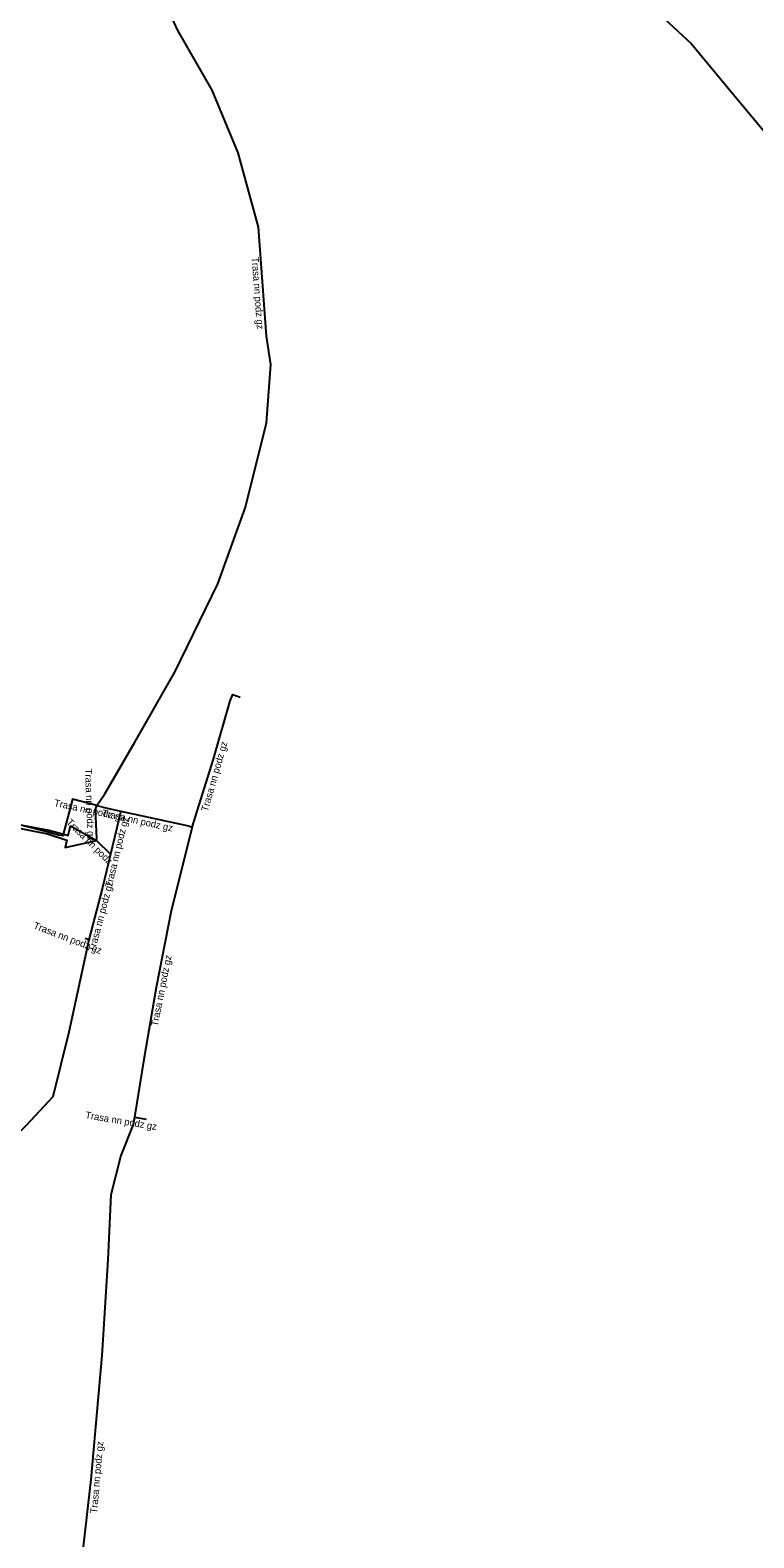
# Model space of a CAD drawing. Extents: x -746106 to -745701, y -1027695 to -1027301.
# Drawn here: x -745858.4 to -745806.6, y -1027605.4 to -1027497.7 of the extents above; entities that cross this region are included whole.
import ezdxf

# ---------------------------------------------------------------- set-up
doc = ezdxf.new("R2010")
doc.units = 0
for name, color, linetype in [('Popiskový text - Ostatní atributy Trasy', 7, 'Continuous'), ('Spojnice NN', 7, 'Continuous'), ('Spojnice VN', 7, 'Continuous')]:
    doc.layers.add(name, color=color, linetype=linetype)

msp = doc.modelspace()

# ---------------------------------------------------------------- linework, layer by layer
at = {"layer": 'Spojnice NN'}
for points in [[(-745833.38, -1027473.7), (-745832.61, -1027474.52), (-745830.56, -1027477.68), (-745830.02, -1027478.96), (-745827.99, -1027481.12), (-745826.54, -1027481.65), (-745825.7, -1027482.38), (-745822.31, -1027485.93), (-745822.27, -1027486.77), (-745822.24, -1027487.41), (-745817.88, -1027491.99), (-745814.57, -1027495.33), (-745813.05, -1027496.89), (-745811.1, -1027498.69), (-745808.13, -1027502.3), (-745805.97, -1027504.9), (-745801.77, -1027509.96)], [(-745853.61, -1027553.12), (-745853.04, -1027552.29), (-745850.88, -1027548.6), (-745848.01, -1027543.54), (-745844.95, -1027537.29), (-745842.98, -1027531.81), (-745841.48, -1027525.78), (-745841.16, -1027521.62), (-745841.47, -1027519.58), (-745842.05, -1027511.8), (-745843.5, -1027506.49), (-745845.35, -1027502.01), (-745847.83, -1027497.69), (-745851.14, -1027490.42), (-745851.64, -1027489.29), (-745851.73, -1027488.18), (-745850.5, -1027485.82), (-745849.88, -1027484.09), (-745850.26, -1027482.81), (-745850.23, -1027482.2)], [(-745853.61, -1027553.12), (-745855.35, -1027552.67), (-745856.03, -1027555.3), (-745856.34, -1027555.24), (-745857.62, -1027554.88), (-745859.38, -1027554.44), (-745860.45, -1027553.37), (-745862.22, -1027551.01), (-745863.97, -1027548.54), (-745864.71, -1027547.66), (-745867.54, -1027543.32), (-745868.03, -1027543.12), (-745868.49, -1027543.06), (-745873.93, -1027545.55), (-745875.45, -1027546.09), (-745878.52, -1027546.57), (-745882.46, -1027546.81)], [(-745846.79, -1027554.68), (-745845.29, -1027549.89), (-745844.07, -1027545.64), (-745843.89, -1027545.19), (-745843.35, -1027545.39)], [(-745853.62, -1027555.63), (-745853.61, -1027555.49), (-745853.69, -1027553.42), (-745853.61, -1027553.12)], [(-745853.61, -1027553.12), (-745852.86, -1027553.32), (-745851.88, -1027553.53)], [(-745851.88, -1027553.53), (-745852.62, -1027556.61)], [(-745851.88, -1027553.53), (-745847.04, -1027554.58), (-745846.79, -1027554.68)], [(-745853.62, -1027555.63), (-745852.62, -1027556.61)], [(-745846.79, -1027554.68), (-745848.28, -1027560.64), (-745849.36, -1027566.13), (-745850.25, -1027571.26), (-745850.92, -1027575.4)], [(-745852.62, -1027556.61), (-745853.19, -1027558.97), (-745854.18, -1027562.73)], [(-745854.18, -1027562.73), (-745855.6, -1027569.32), (-745856.75, -1027573.94), (-745858.67, -1027576.02), (-745861.33, -1027578.57), (-745861.54, -1027578.95), (-745867.09, -1027584.25), (-745871.75, -1027588.63)], [(-745854.18, -1027562.73), (-745854.44, -1027562.63)], [(-745850.92, -1027575.4), (-745851, -1027575.91), (-745851.88, -1027578.14), (-745852.59, -1027580.94), (-745852.82, -1027585.59), (-745853.25, -1027592.42), (-745854.02, -1027601.29), (-745854.78, -1027607.76), (-745855.21, -1027613.64), (-745855.28, -1027615.4), (-745855.13, -1027618.47), (-745856.34, -1027624.29)], [(-745850.92, -1027575.4), (-745850.08, -1027575.54)]]:
    msp.add_lwpolyline(points, dxfattribs=at)
at = {"layer": 'Spojnice VN'}
for points in [[(-745858.94, -1027554.53), (-745857.04, -1027554.88), (-745855.96, -1027555.17), (-745855.66, -1027555.27), (-745855.48, -1027554.57), (-745853.62, -1027555.63)], [(-745859.04, -1027554.77), (-745857.13, -1027555.14), (-745855.74, -1027555.59), (-745855.86, -1027556.12), (-745853.62, -1027555.63)]]:
    msp.add_lwpolyline(points, dxfattribs=at)

# ---------------------------------------------------------------- texts
at = {"layer": 'Popiskový text - Ostatní atributy Trasy'}
for s, rotation, p in [('Trasa nn podz gz', 274.2668, (-745842.54, -1027513.96)), ('Trasa nn podz gz', 73.9834, (-745845.68, -1027553.59)), ('Trasa nn podz gz', 272.0932, (-745854.45, -1027550.5)), ('Trasa nn podz gz', 347.9052, (-745856.69, -1027553.16)), ('Trasa nn podz gz', 347.7598, (-745853.27, -1027553.89)), ('Trasa nn podz', 315.2676, (-745855.81, -1027554.37)), ('Trasa nn podz gz', 76.458, (-745852.53, -1027559.01)), ('Trasa nn podz gz', 75.2489, (-745853.74, -1027563.61)), ('Trasa nn podz gz', 338.9625, (-745858.18, -1027561.89)), ('Trasa nn podz gz', 78.8708, (-745849.25, -1027568.93)), ('Trasa nn podz gz', 350.5377, (-745854.45, -1027575.47)), ('Trasa nn podz gz', 85.0386, (-745853.58, -1027603.72))]:
    msp.add_text(s, height=0.5, rotation=rotation, dxfattribs=at).set_placement(p)

doc.saveas('drawing.dxf')
